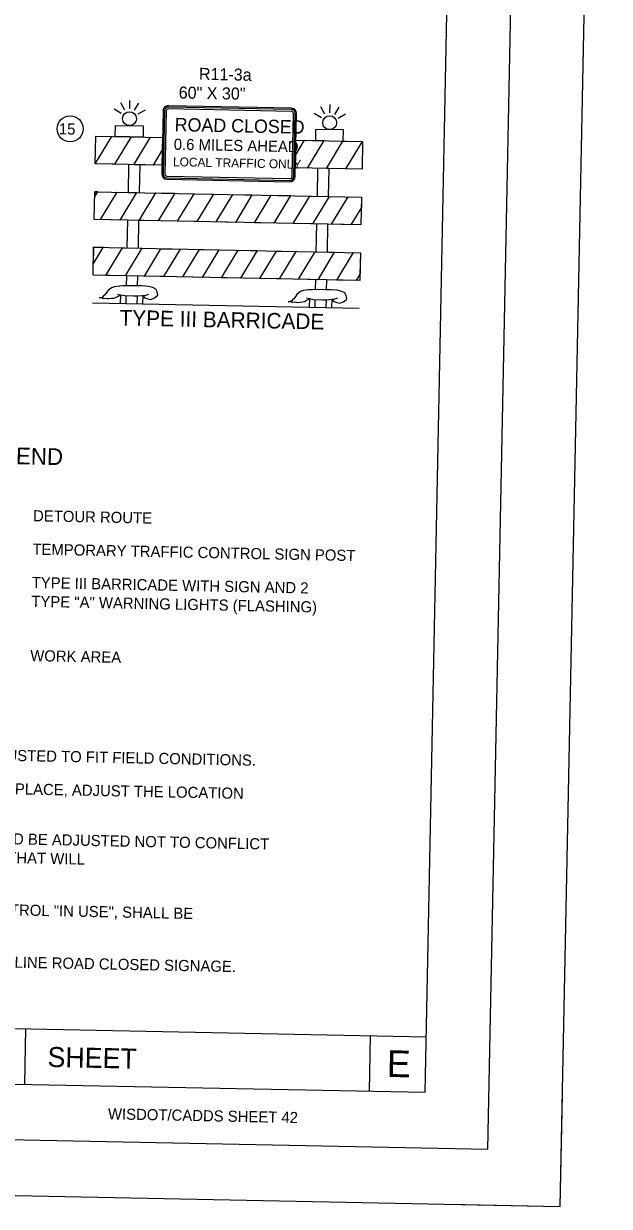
# Model space of a CAD drawing. Extents: x 299354 to 1325680, y 96128 to 228242.
# Drawn here: x 1323046 to 1325680, y 143563 to 148877 of the extents above; entities that cross this region are included whole.
import ezdxf

# ---------------------------------------------------------------- set-up
doc = ezdxf.new("R2010")
doc.units = 0
for name, color, linetype in [('CA-TEXT', 7, 'Continuous'), ('P_SGN_Cell', 7, 'Continuous'), ('PLT_Sheet_Border', 7, 'Continuous'), ('PLT_Sheet_Info', 7, 'Continuous')]:
    doc.layers.add(name, color=color, linetype=linetype)

msp = doc.modelspace()

# ---------------------------------------------------------------- linework, layer by layer
at = {"layer": 'CA-TEXT'}
msp.add_circle((1323255.3, 148404.9), 58.6, dxfattribs=at)
at = {"layer": 'P_SGN_Cell'}
for p, q in [((1323484.8, 148473.1), (1323452.7, 148492.5)), ((1323501.2, 148488.8), (1323483.1, 148521.7)), ((1323523.2, 148494.3), (1323523.9, 148531.7)), ((1323544.9, 148488), (1323564.3, 148520)), ((1323560.6, 148471.6), (1323593.4, 148489.7)), ((1323672.9, 148485.4), (1323667.2, 148202.2)), ((1323679.2, 148485.1), (1323673.5, 148202.1)), ((1323687, 148484.9), (1323681.3, 148201.9)), ((1324249.7, 148483.2), (1323696.5, 148494.3)), ((1324249.9, 148491), (1323696.7, 148502.1)), ((1324250, 148497.2), (1323696.8, 148508.4)), ((1324401, 148470.7), (1324382.9, 148503.6)), ((1324423, 148476.1), (1324423.7, 148513.6)), ((1324444.7, 148469.8), (1324464.1, 148501.9)), ((1324253.2, 148190.4), (1324258.9, 148473.6)), ((1324261, 148190.2), (1324266.7, 148473.4)), ((1324267.3, 148190.1), (1324273, 148473.3)), ((1324384.6, 148455), (1324352.6, 148474.4)), ((1324460.4, 148453.5), (1324493.3, 148471.6)), ((1323518.1, 148244.3), (1323515.6, 148119.3)), ((1323568.1, 148243.3), (1323565.6, 148118.3)), ((1324367.9, 148227.2), (1324365.4, 148102.2)), ((1324417.9, 148226.2), (1324415.4, 148101.2)), ((1323690.2, 148178.3), (1324243.4, 148167.1)), ((1323690.3, 148184.5), (1324243.5, 148173.4)), ((1323690.5, 148192.3), (1324243.7, 148181.2)), ((1323513.1, 147994.4), (1323510.6, 147869.4)), ((1323563.1, 147993.3), (1323560.6, 147868.4)), ((1324362.9, 147977.2), (1324360.4, 147852.3)), ((1324412.9, 147976.2), (1324410.4, 147851.3)), ((1323508.1, 147744.4), (1323507.2, 147700.3)), ((1323558, 147743.4), (1323557.2, 147700.4)), ((1324357.9, 147727.3), (1324357, 147683.1)), ((1324407.9, 147726.3), (1324407, 147682.1)), ((1323481.3, 147659.5), (1323480.5, 147619.9)), ((1323506.3, 147655.3), (1323505.5, 147619.4)), ((1323556.3, 147654.3), (1323555.5, 147618.4)), ((1323581.3, 147656.5), (1323580.5, 147617.9)), ((1324331.2, 147642.4), (1324330.4, 147602.8)), ((1324356.1, 147638.2), (1324355.4, 147602.3)), ((1324406.1, 147637.6), (1324405.4, 147601.3)), ((1324431.1, 147639.4), (1324430.4, 147600.8)), ((1323355.6, 147622.5), (1324555.3, 147598.3))]:
    msp.add_line(p, q, dxfattribs=at)
for points in [[(1323459.2, 148420.5), (1323584.1, 148418), (1323583.1, 148368), (1323458.1, 148370.5)], [(1324483.9, 148399.9), (1324359, 148402.4), (1324358, 148352.4), (1324482.9, 148349.9)], [(1323368.2, 148247.3), (1323442.8, 148370.8), (1323529.4, 148369.1), (1323454.7, 148245.6)], [(1324407.2, 148226.4), (1324481.8, 148349.9), (1324568.4, 148348.2), (1324493.8, 148224.7)], [(1323365.6, 148122.3), (1324565.4, 148098.2), (1324562.9, 147973.2), (1323363.1, 147997.4)], [(1323380.1, 148122.1), (1323365.6, 148122.3), (1323365.1, 148097.4)], [(1323392, 147996.8), (1323466.7, 148120.3), (1323553.2, 148118.6), (1323478.6, 147995.1)], [(1323565.2, 147993.3), (1323639.8, 148116.8), (1323726.4, 148115.1), (1323651.7, 147991.6)], [(1323738.3, 147989.8), (1323813, 148113.3), (1323899.6, 148111.6), (1323824.9, 147988.1)], [(1323911.5, 147986.3), (1323986.2, 148109.9), (1324072.7, 148108.1), (1323998.1, 147984.6)], [(1324084.7, 147982.9), (1324159.3, 148106.4), (1324245.9, 148104.6), (1324171.2, 147981.1)], [(1324257.8, 147979.4), (1324332.5, 148102.9), (1324419.1, 148101.1), (1324344.4, 147977.6)], [(1324431, 147975.9), (1324505.7, 148099.4), (1324565.4, 148098.2), (1324564.5, 148051.7), (1324517.6, 147974.1)], [(1323360.6, 147872.4), (1324560.4, 147848.2), (1324557.8, 147723.3), (1323358.1, 147747.4)], [(1323403.9, 147871.5), (1323360.6, 147872.4), (1323359.1, 147797.4)], [(1323415.8, 147746.3), (1323490.5, 147869.8), (1323577.1, 147868), (1323502.4, 147744.5)], [(1323589, 147742.8), (1323663.7, 147866.3), (1323750.2, 147864.6), (1323675.6, 147741)], [(1323762.2, 147739.3), (1323836.8, 147862.8), (1323923.4, 147861.1), (1323848.7, 147737.5)], [(1323935.3, 147735.8), (1324010, 147859.3), (1324096.6, 147857.6), (1324021.9, 147734.1)], [(1324108.5, 147732.3), (1324183.2, 147855.8), (1324269.7, 147854.1), (1324195.1, 147730.6)], [(1324281.7, 147728.8), (1324356.3, 147852.4), (1324442.9, 147850.6), (1324368.2, 147727.1)], [(1324541.4, 147723.6), (1324454.8, 147725.3), (1324529.5, 147848.9), (1324560.4, 147848.2), (1324558.4, 147751.7)]]:
    msp.add_lwpolyline(points, close=True, dxfattribs=at)
for points in [[(1323668, 148241.3), (1323368.2, 148247.3), (1323370.7, 148372.3), (1323670.5, 148366.3)], [(1323669.4, 148310.7), (1323627.9, 148242.1), (1323541.3, 148243.8), (1323616, 148367.4), (1323670.5, 148366.3)], [(1323670.5, 148366.3), (1323668, 148241.3)], [(1323670.5, 148366.3), (1323669.4, 148310.7)], [(1324268.1, 148229.2), (1324270.6, 148354.2)], [(1324270.6, 148354.2), (1324570.4, 148348.1), (1324567.9, 148223.2), (1324268.1, 148229.2)], [(1324269.3, 148288.2), (1324308.7, 148353.4), (1324395.3, 148351.7), (1324320.6, 148228.2), (1324268.1, 148229.2)], [(1324268.1, 148229.2), (1324269.3, 148288.2)], [(1323583.8, 147655.2), (1323590.5, 147646), (1323605.2, 147641.1), (1323617.7, 147638.6), (1323635, 147645.1), (1323646.6, 147654), (1323650.1, 147659.2), (1323646.9, 147672.2), (1323640.3, 147684.5), (1323626.8, 147691.7), (1323606.3, 147696.7), (1323579, 147698.7), (1323553.9, 147699.2), (1323519.6, 147699.9), (1323492.2, 147698.9), (1323478.5, 147698.5), (1323454.4, 147695.1), (1323441.8, 147690.8), (1323424.4, 147677.5), (1323419.7, 147670.7), (1323409.2, 147657.2), (1323405.7, 147654.3), (1323399.8, 147645.3)], [(1323478.8, 147655.8), (1323470.7, 147651.4), (1323456.9, 147644.9), (1323450, 147642.7), (1323439.7, 147642.2), (1323429.4, 147640.8), (1323423.7, 147641), (1323420.3, 147642.6), (1323403.1, 147641.4), (1323403.2, 147642.9), (1323399.8, 147643.7), (1323385, 147645.5)], [(1323468.6, 147662.1), (1323481.7, 147659.5)], [(1323482.2, 147659.4), (1323501.6, 147655.4), (1323540.4, 147653.8), (1323559.8, 147654.2), (1323595.3, 147658.1), (1323609.1, 147662.3)], [(1324328.6, 147638.7), (1324320.5, 147634.3), (1324306.7, 147627.8), (1324299.8, 147625.6), (1324289.5, 147625.1), (1324279.2, 147623.7), (1324273.5, 147623.9), (1324270.1, 147625.4), (1324253, 147624.3), (1324253, 147625.8), (1324249.6, 147626.6), (1324234.8, 147628.4)], [(1324433.6, 147638.1), (1324440.3, 147628.9), (1324455, 147624), (1324467.5, 147621.5), (1324484.8, 147628), (1324496.4, 147636.9), (1324499.9, 147642.1), (1324496.7, 147655.1), (1324490.1, 147667.4), (1324476.6, 147674.6), (1324456.1, 147679.5), (1324428.8, 147681.6), (1324403.7, 147682.1), (1324369.4, 147682.8), (1324342, 147681.8), (1324328.3, 147681.4), (1324304.3, 147678), (1324291.6, 147673.7), (1324274.2, 147660.4), (1324269.5, 147653.6), (1324259, 147640.1), (1324255.5, 147637.2), (1324249.6, 147628.1)], [(1324318.4, 147645), (1324331.5, 147642.3)], [(1324332, 147642.2), (1324351.4, 147638.3), (1324390.2, 147636.7), (1324409.6, 147637.1), (1324445.1, 147641), (1324458.9, 147645.2)]]:
    msp.add_lwpolyline(points, dxfattribs=at)
for centre in [(1323522.3, 148450.5), (1324422.1, 148432.4)]:
    msp.add_circle(centre, 31.2, dxfattribs=at)
for centre, radius, start, end in [((1323696.3, 148484.9), 23.4, 88.8468, 178.8468), ((1323696.3, 148484.9), 17.2, 88.8468, 178.8468), ((1323696.3, 148484.9), 9.38, 88.8468, 179.9247), ((1324249.5, 148473.8), 9.38, 358.8468, 88.8468), ((1324249.5, 148473.8), 17.2, 358.8468, 88.8468), ((1324249.5, 148473.8), 23.4, 358.8468, 88.8468), ((1323690.6, 148201.7), 23.4, 178.8468, 268.8468), ((1323690.6, 148201.7), 17.2, 178.8468, 268.8468), ((1323690.6, 148201.7), 9.38, 178.8468, 268.8468), ((1324243.8, 148190.6), 23.4, 268.8468, 358.8468), ((1324243.8, 148190.6), 17.2, 268.8468, 358.8468), ((1324243.8, 148190.6), 9.38, 268.8468, 358.8468)]:
    msp.add_arc(centre, radius, start, end, dxfattribs=at)
for points in [[(1323386.1, 147645.5), (1323396.4, 147647.6), (1323403.3, 147650.5)], [(1324235.9, 147628.4), (1324246.2, 147630.5), (1324253.1, 147633.4)]]:
    msp.add_spline(points, degree=3, dxfattribs=at)
at = {"layer": 'PLT_Sheet_Border'}
for points in [[(1308461.6, 143905.4), (1325458.1, 143563.1), (1325679.6, 154560.9), (1308683.1, 154903.2)], [(1308586.6, 144153), (1325133.2, 143819.7), (1325344.6, 154317.6), (1308798, 154650.9)]]:
    msp.add_lwpolyline(points, close=True, dxfattribs=at)
at = {"layer": 'PLT_Sheet_Info'}
for p, q in [((1324850.8, 144075.5), (1325052.2, 154073.4)), ((1309109, 144642.6), (1324855.8, 144325.4)), ((1309104, 144392.6), (1324850.8, 144075.5)), ((1323051.2, 144111.7), (1323056.2, 144361.7)), ((1324600.9, 144080.5), (1324605.9, 144330.5)), ((1325458.1, 143563.1), (1325468.2, 144063)), ((1324958.2, 143573.2), (1325458.1, 143563.1))]:
    msp.add_line(p, q, dxfattribs=at)

# ---------------------------------------------------------------- texts
at = {"layer": 'CA-TEXT'}
for s, height, rotation, p in [('15', 50, 358.8468, (1323204.1, 148380.3)), ('LEGEND', 75, 358.8468, (1322810.3, 146902)), ('DETOUR ROUTE', 50, 358.8468, (1323088.1, 146641.6)), ('TEMPORARY TRAFFIC CONTROL SIGN POST', 50, 358.8468, (1323085.1, 146491.6)), ('TYPE III BARRICADE WITH SIGN AND 2', 50, 358.8468, (1323082.1, 146341.7)), ('TYPE "A" WARNING LIGHTS (FLASHING)', 50, 358.8468, (1323080.4, 146257.2)), ('WORK AREA', 50, 358.8468, (1323075.5, 146013.2)), ('THE EXACT NUMBER, LOCATION AND SPACING OF ALL SIGNS SHALL BE ADJUSTED TO FIT FIELD CONDITIONS.', 50, 358.8462, (1320468.9, 145615.4)), ('IF THERE ARE EXISTING ROUTE MARKER ASSEMBLIES THAT WILL REMAIN IN PLACE, ADJUST THE LOCATION ', 50, 358.8462, (1320465.9, 145465.5)), ('THE SPACING BETWEEN THE TRAFFIC CONTROL AND DETOUR SIGNS SHOULD BE ADJUSTED NOT TO CONFLICT', 50, 358.8462, (1320461.4, 145240.5)), ("WITH AND TO PROVIDE A MINIMUM OF 200' CLEARANCE TO EXISTING SIGNS THAT WILL", 50, 358.8462, (1320459.7, 145156)), ('ANY SIGNS TEMPORARY OR EXISTING, WHICH CONFLICT WITH TRAFFIC CONTROL "IN USE", SHALL BE', 50, 358.8462, (1320455, 144921.5)), ('FOLLOW SDD "BARRICADES AND SIGNS FOR MAINLINE CLOSURES" FOR MAINLINE ROAD CLOSED SIGNAGE.', 50, 358.8462, (1320450.2, 144687))]:
    msp.add_text(s, height=height, rotation=rotation, dxfattribs=at).set_placement(p)
at = {"layer": 'P_SGN_Cell'}
for s, height, rotation, p in [('R11-3a', 54, 358.8462, (1323833.9, 148625.3)), ('60" X 30"', 54, 358.8462, (1323742.9, 148541.4)), ('ROAD CLOSED', 60, 358.8462, (1323724.7, 148394.5)), ('0.6 MILES AHEAD', 50, 358.8462, (1323720.8, 148310.9)), ('LOCAL TRAFFIC ONLY', 40, 358.8462, (1323717.5, 148237.1)), ('TYPE III BARRICADE', 70, 358.8468, (1323476.8, 147521.5))]:
    msp.add_text(s, height=height, rotation=rotation, dxfattribs=at).set_placement(p)
at = {"layer": 'PLT_Sheet_Info'}
for s, height, p in [('SHEET ', 90, (1323152.8, 144189.7)), ('E', 120, (1324678.1, 144144.8)), ('WISDOT/CADDS SHEET 42', 50, (1323424.9, 143954.2))]:
    msp.add_text(s, height=height, rotation=358.8462, dxfattribs=at).set_placement(p)

doc.saveas('drawing.dxf')
